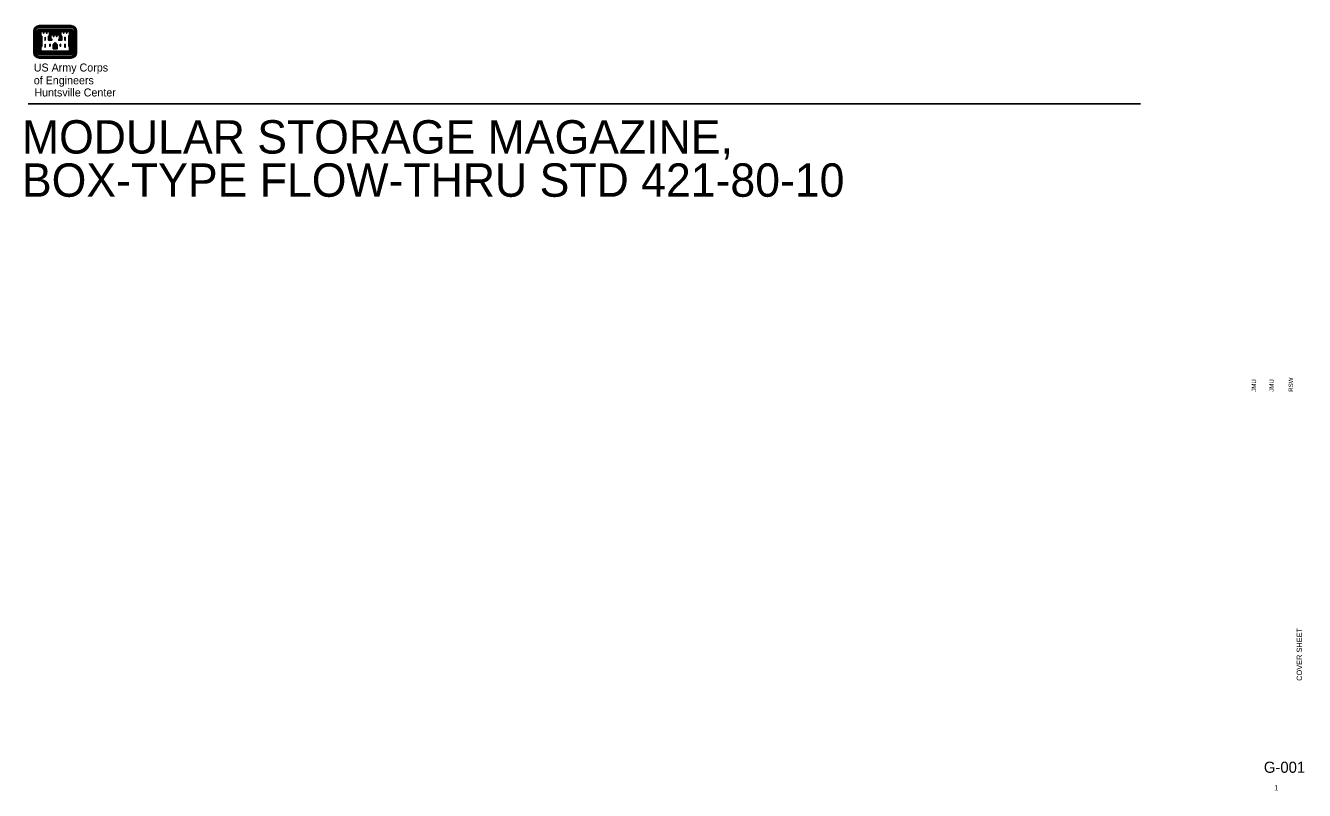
# Model space of a CAD drawing. Extents: x 0.3 to 2.69, y 0.14 to 1.57.
import ezdxf

# ---------------------------------------------------------------- set-up
doc = ezdxf.new("R2010")
doc.units = 0
doc.layers.add('G-ANNO-TEXT', color=7, linetype='Continuous')
doc.layers.add('G-ANNO-TTLB', color=7, linetype='Continuous')

msp = doc.modelspace()

# ---------------------------------------------------------------- linework, layer by layer
at = {"layer": 'G-ANNO-TEXT'}
msp.add_line((0.3008, 1.4245), (2.3865, 1.4245), dxfattribs=at)
at = {"layer": 'G-ANNO-TTLB'}
for p, q in [((0.3116, 1.5605), (0.3116, 1.5206)), ((0.3123, 1.5605), (0.3123, 1.5206)), ((0.3132, 1.5605), (0.3132, 1.5206)), ((0.314, 1.5605), (0.314, 1.5206)), ((0.3148, 1.5605), (0.3148, 1.5206)), ((0.3182, 1.5605), (0.3182, 1.5206)), ((0.3191, 1.5605), (0.3191, 1.5206)), ((0.3199, 1.5605), (0.3199, 1.5206)), ((0.3208, 1.5605), (0.3208, 1.5206)), ((0.3216, 1.5605), (0.3216, 1.5206)), ((0.3813, 1.5711), (0.3222, 1.5711)), ((0.3813, 1.5704), (0.3222, 1.5704)), ((0.3813, 1.5696), (0.3222, 1.5696)), ((0.3813, 1.5688), (0.3222, 1.5688)), ((0.3813, 1.5679), (0.3222, 1.5679)), ((0.3813, 1.5646), (0.3222, 1.5646)), ((0.3813, 1.5637), (0.3222, 1.5637)), ((0.3813, 1.5628), (0.3222, 1.5628)), ((0.3813, 1.562), (0.3222, 1.562)), ((0.3813, 1.5612), (0.3222, 1.5612)), ((0.3224, 1.5605), (0.3224, 1.5209)), ((0.3233, 1.5605), (0.3233, 1.5218)), ((0.3425, 1.5603), (0.3608, 1.5603)), ((0.3425, 1.5595), (0.3608, 1.5595)), ((0.3425, 1.5588), (0.3608, 1.5588)), ((0.3802, 1.5605), (0.3802, 1.5218)), ((0.381, 1.5605), (0.381, 1.5209)), ((0.3818, 1.5605), (0.3818, 1.5206)), ((0.3827, 1.5605), (0.3827, 1.5206)), ((0.3836, 1.5605), (0.3836, 1.5206)), ((0.3844, 1.5605), (0.3844, 1.5206)), ((0.3852, 1.5605), (0.3852, 1.5206)), ((0.3886, 1.5605), (0.3886, 1.5206)), ((0.3895, 1.5605), (0.3895, 1.5206)), ((0.3903, 1.5605), (0.3903, 1.5206)), ((0.3911, 1.5605), (0.3911, 1.5206)), ((0.3917, 1.5605), (0.3917, 1.5206)), ((0.324, 1.5521), (0.324, 1.5316)), ((0.3248, 1.5512), (0.3248, 1.5326)), ((0.3425, 1.5578), (0.3608, 1.5578)), ((0.3425, 1.557), (0.3608, 1.557)), ((0.3425, 1.5562), (0.3608, 1.5562)), ((0.3425, 1.5553), (0.3608, 1.5553)), ((0.3787, 1.5512), (0.3787, 1.5326)), ((0.3794, 1.552), (0.3794, 1.5318)), ((0.3813, 1.52), (0.3222, 1.52)), ((0.3813, 1.5192), (0.3222, 1.5192)), ((0.3813, 1.5183), (0.3222, 1.5183)), ((0.3813, 1.5175), (0.3222, 1.5175)), ((0.3813, 1.5167), (0.3222, 1.5167)), ((0.3813, 1.5132), (0.3222, 1.5132)), ((0.3813, 1.5124), (0.3222, 1.5124)), ((0.3813, 1.5116), (0.3222, 1.5116)), ((0.3813, 1.5108), (0.3222, 1.5108)), ((0.381, 1.5209), (0.3224, 1.5209)), ((0.3802, 1.5218), (0.3233, 1.5218)), ((0.3477, 1.5275), (0.3477, 1.534)), ((0.3477, 1.5275), (0.3557, 1.5275)), ((0.3486, 1.5275), (0.3486, 1.534)), ((0.3494, 1.5275), (0.3494, 1.534)), ((0.3503, 1.5275), (0.3503, 1.534)), ((0.3512, 1.5275), (0.3512, 1.534)), ((0.3523, 1.5275), (0.3523, 1.534)), ((0.3531, 1.5275), (0.3531, 1.534)), ((0.354, 1.5275), (0.354, 1.534)), ((0.3548, 1.5275), (0.3548, 1.534)), ((0.3557, 1.5275), (0.3557, 1.534)), ((0.3813, 1.5101), (0.3222, 1.5101))]:
    msp.add_line(p, q, dxfattribs=at)
for points in [[(0.324, 1.5605), (0.324, 1.5529), (0.3257, 1.5512), (0.3257, 1.5326), (0.324, 1.5308), (0.324, 1.5223), (0.3795, 1.5223), (0.3795, 1.5308), (0.3777, 1.5326), (0.3777, 1.5512), (0.3795, 1.5529), (0.3795, 1.5605), (0.3722, 1.5605), (0.3665, 1.5605), (0.3613, 1.5605), (0.3613, 1.5529), (0.3631, 1.5512), (0.3631, 1.5445), (0.3591, 1.5445), (0.3591, 1.5451), (0.3608, 1.5468), (0.3608, 1.5544), (0.3534, 1.5544), (0.3478, 1.5544), (0.3425, 1.5544), (0.3425, 1.5468), (0.3443, 1.5451), (0.3443, 1.5445), (0.3403, 1.5445), (0.3403, 1.5512), (0.3421, 1.5529), (0.3421, 1.5605), (0.3346, 1.5605), (0.329, 1.5605), (0.324, 1.5605)], [(0.3248, 1.5597), (0.3248, 1.5533), (0.3265, 1.5515), (0.3265, 1.5322), (0.3248, 1.5305), (0.3248, 1.5233), (0.3787, 1.5233), (0.3787, 1.5305), (0.377, 1.5322), (0.377, 1.5515), (0.3787, 1.5533), (0.3787, 1.5597), (0.3735, 1.5597), (0.3735, 1.5567), (0.373, 1.5567), (0.373, 1.5597), (0.3679, 1.5597), (0.3679, 1.5567), (0.3674, 1.5567), (0.3674, 1.5597), (0.3622, 1.5597), (0.3622, 1.5533), (0.3639, 1.5515), (0.3639, 1.5436), (0.3583, 1.5436), (0.3583, 1.5455), (0.36, 1.5471), (0.36, 1.5537), (0.3548, 1.5537), (0.3548, 1.5506), (0.3543, 1.5506), (0.3543, 1.5537), (0.3491, 1.5537), (0.3491, 1.5506), (0.3486, 1.5506), (0.3486, 1.5537), (0.3435, 1.5537), (0.3435, 1.5471), (0.3452, 1.5455), (0.3452, 1.5436), (0.3394, 1.5436), (0.3394, 1.5515), (0.3412, 1.5533), (0.3412, 1.5597), (0.3361, 1.5597), (0.3361, 1.5567), (0.3356, 1.5567), (0.3356, 1.5597), (0.3303, 1.5597), (0.3303, 1.5567), (0.3299, 1.5567), (0.3299, 1.5597), (0.3248, 1.5597)], [(0.3327, 1.5493), (0.3327, 1.5436), (0.3332, 1.5436), (0.3332, 1.5493), (0.3327, 1.5493)], [(0.3327, 1.5362), (0.3327, 1.5306), (0.3332, 1.5306), (0.3332, 1.5362), (0.3327, 1.5362)], [(0.3417, 1.5513), (0.3411, 1.5508), (0.3411, 1.5452), (0.343, 1.5452), (0.3417, 1.5465), (0.3417, 1.5514)], [(0.3416, 1.5362), (0.3416, 1.5324), (0.3422, 1.5324), (0.3422, 1.5362), (0.3416, 1.5362)], [(0.3617, 1.5513), (0.3622, 1.5508), (0.3622, 1.5452), (0.3605, 1.5452), (0.3617, 1.5465), (0.3617, 1.5514)], [(0.3617, 1.5362), (0.3617, 1.5324), (0.3612, 1.5324), (0.3612, 1.5362), (0.3617, 1.5362)], [(0.3707, 1.5493), (0.3707, 1.5436), (0.3701, 1.5436), (0.3701, 1.5493), (0.3707, 1.5493)], [(0.3707, 1.5362), (0.3707, 1.5306), (0.3701, 1.5306), (0.3701, 1.5362), (0.3707, 1.5362)]]:
    msp.add_lwpolyline(points, dxfattribs=at)
for centre, major_axis, start_param, end_param in [((0.3221, 1.5606), (-0.0104, 0), 4.712389, 6.283185), ((0.3221, 1.5606), (-0.00984, 0), 4.712389, 6.283185), ((0.3221, 1.5606), (-0.00899, 0), 4.712389, 6.283185), ((0.3221, 1.5606), (-0.00815, 0), 4.712389, 6.283185), ((0.3221, 1.5606), (-0.0073, 0), 4.712389, 6.283185), ((0.3221, 1.5606), (-0.00392, 0), 4.712389, 6.283185), ((0.3221, 1.5606), (-0.00307, 0), 4.712389, 6.283185), ((0.3221, 1.5606), (-0.00222, 0), 4.712389, 6.283185), ((0.3221, 1.5606), (0.00138, 0), 1.570796, 3.141593), ((0.3221, 1.5606), (-0.000532, 0), 4.712389, 6.283185), ((0.3813, 1.5606), (-0.0104, 0), 3.141593, 4.712389), ((0.3813, 1.5606), (0.00984, 0), 0, 1.570796), ((0.3813, 1.5606), (0.00899, 0), 0, 1.570796), ((0.3813, 1.5606), (0.00815, 0), 0, 1.570796), ((0.3813, 1.5606), (0.0073, 0), 0, 1.570796), ((0.3813, 1.5606), (-0.00392, 0), 3.141593, 4.712389), ((0.3813, 1.5606), (-0.00307, 0), 3.141593, 4.712389), ((0.3813, 1.5606), (-0.00222, 0), 3.141593, 4.712389), ((0.3813, 1.5606), (-0.00138, 0), 3.141593, 4.712389), ((0.3813, 1.5606), (-0.000532, 0), 3.141593, 4.712389), ((0.3532, 1.5336), (0.00541, 0), 1.844255, 3.072783), ((0.3532, 1.5336), (-0.00457, 0), 4.947481, 6.214375), ((0.3532, 1.5336), (-0.00372, 0), 4.947481, 6.214375), ((0.3532, 1.5336), (-0.00288, 0), 4.947481, 6.214375), ((0.3502, 1.5336), (0.00203, 0), 0.06881, 1.335704), ((0.3502, 1.5336), (0.00288, 0), 0.06881, 1.335704), ((0.3502, 1.5336), (-0.00372, 0), 3.210403, 4.477297), ((0.3532, 1.5336), (-0.00203, 0), 4.947481, 6.214375), ((0.3502, 1.5336), (0.00457, 0), 0.06881, 1.335704), ((0.3502, 1.5336), (0.00541, 0), 0.06881, 1.298435), ((0.3221, 1.5206), (0.0104, 0), 3.141593, 4.712389), ((0.3221, 1.5206), (0.00984, 0), 3.141593, 4.712389), ((0.3221, 1.5206), (-0.00899, 0), 0, 1.570796), ((0.3221, 1.5206), (0.00815, 0), 3.141593, 4.712389), ((0.3221, 1.5206), (0.0073, 0), 3.141593, 4.712389), ((0.3221, 1.5206), (0.00392, 0), 3.141593, 4.712389), ((0.3221, 1.5206), (0.00307, 0), 3.141593, 4.712389), ((0.3221, 1.5206), (0.00222, 0), 3.141593, 4.712389), ((0.3221, 1.5206), (0.00138, 0), 3.141593, 4.712389), ((0.3221, 1.5206), (0.000532, 0), 3.141593, 4.712389), ((0.3813, 1.5206), (0.0104, 0), 4.712389, 6.283185), ((0.3813, 1.5206), (0.00392, 0), 4.712389, 6.283185), ((0.3813, 1.5206), (0.00307, 0), 4.712389, 6.283185), ((0.3813, 1.5206), (0.00222, 0), 4.712389, 6.283185), ((0.3813, 1.5206), (0.00138, 0), 4.712389, 6.283185), ((0.3813, 1.5206), (0.000532, 0), 4.712389, 6.283185), ((0.3813, 1.5206), (0.0073, 0), 4.712389, 6.283185), ((0.3813, 1.5206), (0.00815, 0), 4.712389, 6.283185), ((0.3813, 1.5206), (0.00899, 0), 4.712389, 6.283185), ((0.3813, 1.5206), (0.00984, 0), 4.712389, 6.283185)]:
    msp.add_ellipse(centre, major_axis=major_axis, ratio=0.999936, start_param=start_param, end_param=end_param, dxfattribs=at)

# ---------------------------------------------------------------- texts
for s, height, p in [('US Army Corps', 0.015, (0.3116, 1.485)), ('of Engineers', 0.015, (0.3116, 1.4611)), ('Huntsville Center', 0.015, (0.3127, 1.4383)), ('MODULAR STORAGE MAGAZINE, ', 0.0625, (0.2894, 1.3313)), ('BOX-TYPE FLOW-THRU STD 421-80-10 ', 0.0625, (0.2894, 1.2504)), ('G-001', 0.02083, (2.6175, 0.1712)), ('1', 0.01, (2.6369, 0.1382))]:
    msp.add_text(s, height=height, dxfattribs=at).set_placement(p)
for s, height, p in [('JMU', 0.00833, (2.603, 0.885)), ('JMU', 0.00833, (2.6359, 0.885)), ('RSW', 0.00833, (2.6722, 0.885)), ('COVER SHEET', 0.01, (2.689, 0.3435))]:
    msp.add_text(s, height=height, rotation=90, dxfattribs=at).set_placement(p)

doc.saveas('drawing.dxf')
